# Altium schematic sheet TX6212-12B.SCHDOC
size A; SheetNumber: 0; SheetTotal: 0
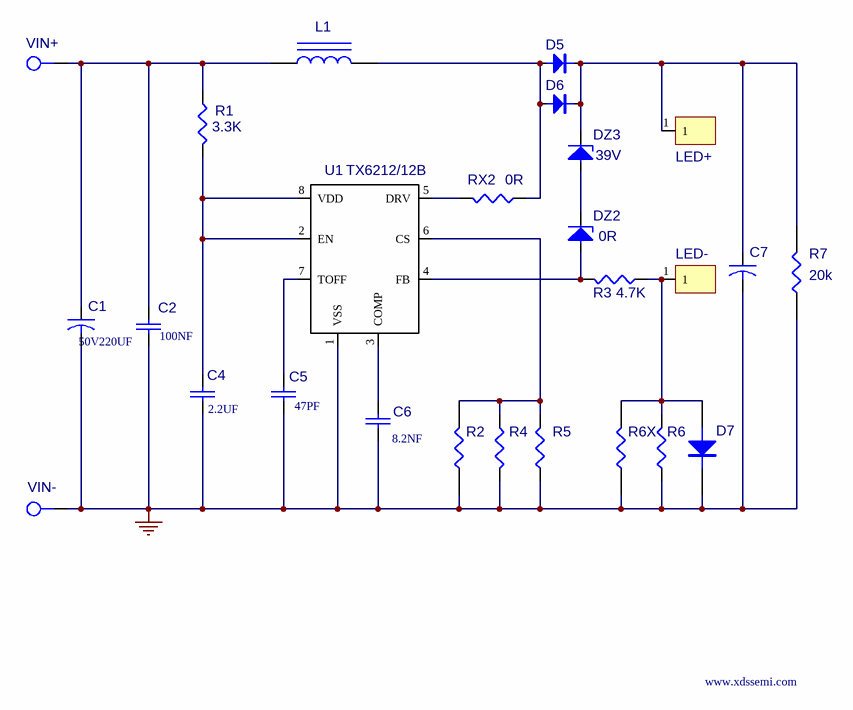
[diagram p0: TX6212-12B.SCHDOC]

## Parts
C1  (no value)  [CINJ]
C2  (no value)  [0805]
C4  (no value)  [0805]
C5  (no value)  [0805]
C6  (no value)  [0805]
C7  (no value)  [CINJ]
D5  (no value)  [SMBJ]
D6  (no value)  [SMBJ]
D7  (no value)
DZ2  0R  [DZJ]
DZ3  39V  [DZJ]
E  LED+  [OUT]
F  LED-  [OUT]
L1  (no value)  [TJJ]
R1  3.3K  [0805]
R2  (no value)
R3  4.7K  [0805]
R4  (no value)  [1206]
R5  (no value)  [1206]
R6  (no value)  [0805]
R6X  (no value)
R7  20k
RX2  0R  [0805]
U1  TX6212/12B  [SO8J]
VIN+  (no value)  [P]
VIN-  (no value)  [P]

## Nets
GND: C1.2 C2.1 C4.1 C5.1 C6.1 C7.2 D7.2(K) R2.1 R4.2 R5.1 R6.1 R6X.1 R7.1 U1.1(VSS) VIN-.P
NetC1_1: C1.1 C2.2 L1.1 R1.1 VIN+.P
NetC4_2: C4.2 R1.2 U1.2(EN) U1.8(VDD)
NetC5_2: C5.2 U1.7(TOFF)
NetC6_2: C6.2 U1.3(COMP)
NetC7_1: C7.1 D5.2(K) D6.2(K) DZ3.2 E.1 R7.2
NetD5_1: D5.1(A) D6.1(A) L1.2 RX2.1
NetD7_1: D7.1(A) F.1 R3.1 R6.2 R6X.2
NetDZ2_1: DZ2.1 R3.2 U1.4(FB)
NetDZ2_2: DZ2.2 DZ3.1
NetR2_2: R2.2 R4.1 R5.2 U1.6(CS)
NetRX2_2: RX2.2 U1.5(DRV)

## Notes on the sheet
- (near C1) 50V220UF
- (near C2) 100NF
- (near C4) 2.2UF
- (near C5) 47PF
- (near C6) 8.2NF
- www.xdssemi.com

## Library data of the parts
C1 C7 = CAPACITOR
C2 C4-C6 = CAP: Capacitor
D5-D7 = DIODE
DZ2 DZ3 = ZENER1: Zener Diode
E F = IN
L1 = INDUCTOR IRON
R1-R6 R6X R7 RX2 = RES1
U1 = Component_1
VIN+ VIN- = P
